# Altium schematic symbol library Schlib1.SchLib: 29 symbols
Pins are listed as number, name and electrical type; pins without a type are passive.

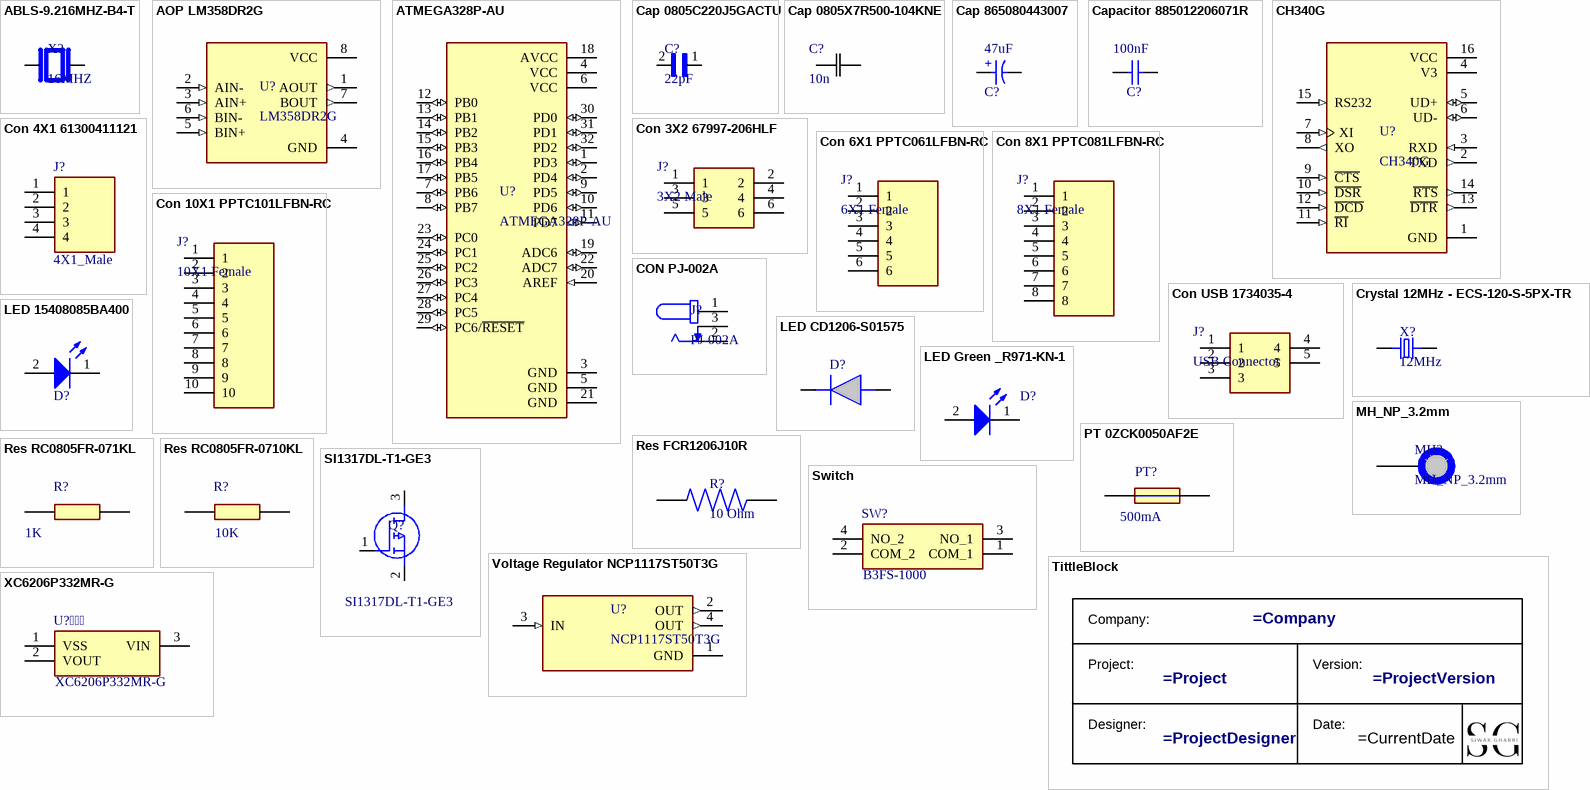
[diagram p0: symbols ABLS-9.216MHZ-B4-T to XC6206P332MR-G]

## ABLS-9.216MHZ-B4-T
designator X?, comment 16MHZ
HC/49US (AT49) SMD LOW PROFILE CRYSTAL; MF: Abracon LLC; MP: ABLS-9.216MHZ-B4-T
footprint XTAL_ABLS-9.216MHZ-B4-T
footprint XTAL_ABLS-9.216MHZ-B4-T
pins: 1, 2

## AOP LM358DR2G
designator U?, comment LM358DR2G
General Purpose Amplifier 2 Circuit - 8-SOIC; MF: ON Semiconductor
footprint SOIC127P600X175-8N
pins: 1 AOUT (out), 2 AIN- (in), 3 AIN+ (in), 4 GND, 5 BIN+ (in), 6 BIN- (in), 7 BOUT (out), 8 VCC (power)

## ATMEGA328P-AU
designator U?
AVR AVRÂ® ATmega Microcontroller IC 8-Bit 20MHz 32KB (16K x 16) FLASH 32-TQFP (7x7); MF: Microchip Technology
footprint QFP80P900X900X120-32N
pins: 1 PD3 (io), 2 PD4 (io), 3 GND (power), 4 VCC (power), 5 GND (power), 6 VCC (power), 7 PB6 (io), 8 PB7 (io), 9 PD5 (io), 10 PD6 (io), 11 PD7 (io), 12 PB0 (io), 13 PB1 (io), 14 PB2 (io), 15 PB3 (io), 16 PB4 (io), 17 PB5 (io), 18 AVCC (power), 19 ADC6 (io), 20 AREF (in), 21 GND (power), 22 ADC7 (io), 23 PC0 (io), 24 PC1 (io), 25 PC2 (io), 26 PC3 (io), 27 PC4 (io), 28 PC5 (io), 29 PC6/~{RESET} (io), 30 PD0 (io), 31 PD1 (io), 32 PD2 (io)

## Cap 0805C220J5GACTU
designator C?, comment 22pF
22pF Â±5% 50V Ceramic Capacitor C0G, NP0 0805 _2012 Metric_; MP: C0805C220J5GACTU; MF: KEMET
footprint CAPC2012X140N
pins: 1, 2

## Cap 0805X7R500-104KNE
designator C?, comment 10n
0.1 µF ±10% 50V Ceramic Capacitor X7R 0805 (2012 Metric); Mfr_Name: Venkel
footprint CAP_C0805_VEN-M
pins: 1, 2

## Cap 865080443007
designator C?, comment 47uF
WCAP-ASLI Aluminum Electrolytic Capacitor, V-Chip, D6.3 x H5.5mm, 47uF, 25V; Manufacturer Part Number: 865080443007; Manufacturer: Wurth Elektronik; Capacitance Tolerance: +/-20%; Dissipation Factor: 14%; Endurance: 2000h; Leakage Current: 11.75uA; Ripple Current: 220mA; Technical Reference: ASED055470M025DVCTBB000
footprint WCAP-ASLI_D6.3H5.5
simulation model 865080443007_47uF
footprint WCAP-ASLI_D6.3H7.7 (Aluminium Electrolytic V-Chip SMT Capacitors, 6.3x7.7mm)
pins: 1 P, 2 N

## Capacitor 885012206071R
designator C?, comment 100nF
WCAP-CSGP Multilayer Ceramic Chip Capacitor, General Purpose, size 0603, X7R, 100nF, 25VDC; Manufacturer Part Number: 885012206071R; Manufacturer: Wurth Elektronik; Case/Size Code: 0603; Capacitance Tolerance: +/-10%; Dissipation Factor: 3.5%; Insulation Resistance: 5GOhm; Rated Voltage (DC): 25V; Technical Reference: X7R0603104K025DFCT20000
footprint WCAP-CSGP_0603_L1.6W0.8H0.8_Reflow
footprint WCAP-CSGP_0603_L1.6W0.8H0.8_Wave
simulation model 0603_885012206071R_100nF
footprint WCAP-CSGP_0603_L1.6W0.8H0.8_Wave (Ceramic Capacitors, 0603, body 1.6x0.8mm)
pins: 1, 2

## CH340G
designator U?
USB Interface Integrated Circuit; MF: WCH
footprint SOIC127P600X180-16N
footprint SOIC127P600X180-16N
pins: 1 GND (power), 2 TXD (out), 3 RXD (in), 4 V3 (power), 5 UD+ (io), 6 UD- (io), 7 XI (in), 8 XO (out), 9 ~{CTS} (in), 10 ~{DSR} (in), 11 ~{RI} (in), 12 ~{DCD} (in), 13 ~{DTR} (out), 14 ~{RTS} (out), 15 RS232 (in), 16 VCC (power)

## Con 3X2 67997-206HLF
designator J?, comment 3X2 Male
Connector; Manufacturer_Name: Amphenol; Manufacturer_Part_Number: 67997-206HLF
footprint HDRV6W67P254_2X3_762X483X858P
pins: 1, 2, 3, 4, 5, 6

## Con 4X1 61300411121
designator J?, comment 4X1_Male
WR-PHD 2.54mm Pin Header THT Straight 4p Wurth Elektronik WR-PHD Series, Series Number 6130, 2.54mm Pitch 4 Way 1 Row Straight PCB Header, Solder Termination; Manufacturer_Part_Number: 61300411121; Geometry.Height: 8.54mm
footprint HDRV4W95P0X254_1X4_1016X254X854P
pins: 1, 2, 3, 4

## Con 6X1 PPTC061LFBN-RC
designator J?, comment 6X1 Female
Connector; Manufacturer_Name: Sullins; Manufacturer_Part_Number: PPTC061LFBN-RC
footprint RHDR6W80P0X254_1X6_1574X254X870P
pins: 1, 2, 3, 4, 5, 6

## Con 8X1 PPTC081LFBN-RC
designator J?, comment 8X1 Female
Connector; Manufacturer_Name: Sullins; Manufacturer_Part_Number: PPTC081LFBN-RC
footprint RHDR8W80P0X254_1X8_2082X254X850P
pins: 1, 2, 3, 4, 5, 6, 7, 8

## Con 10X1 PPTC101LFBN-RC
designator J?, comment 10X1 Female
10 Position Header Connector 0.100" (2.54mm) Through Hole Tin; Manufacturer_Name: Sullins; Manufacturer_Part_Number: PPTC101LFBN-RC
footprint RHDR10W80P0X254_1X10_2590X254X850P
pins: 1, 2, 3, 4, 5, 6, 7, 8, 9, 10

## CON PJ-002A
designator J?, comment PJ-002A
2.0 x 6.5 mm, 2.5 A, Horizontal, Through Hole, Dc Power Jack Connector; MF: CUI Devices
footprint CUI_PJ-002A
footprint CUI_PJ-002A
pins: 1, 2, 3

## Con USB 1734035-4
designator J?, comment USB Connector
Conn Mini USB 2.0 Type B RCP 5 POS 0.8mm Solder RA SMD 5 Terminal 1 Port Automotive T/R; Manufacturer_Name: TE Connectivity; Manufacturer_Part_Number: 1734035-4
footprint 1734035-2USB
footprint 1734035-2USB
pins: 1, 2, 3, 4, 5

## Crystal 12MHz - ECS-120-S-5PX-TR
designator X?, comment 12MHz
12MHz Â±30ppm Crystal Series 50 Ohms HC-49/US; MF: ECS Inc.; MP: ECS-120-S-5PX-TR
footprint XTAL_ECS-120-S-5PX-TR
pins: 1, 2

## LED 15408085BA400
designator D?, comment 15408085BA400  (value not drawn)
WL-SICW SMT Chip LED Infrared Waterclear, size 0805, Infrared, 1.4V, 140°; Manufacturer: Wurth Elektronik; Case/Size Code: 0805; Centroid Wavelength: 845nm; Chip Technology: AlGaAs; Forward Voltage Max: 2V; Peak Wavelength: 850nm; Radiant Intensity: 1.5mW/sr; Radiant Intensity Min: 0.6mW/sr
footprint WL-SICW_0805_L2W1.3H0.8
simulation model 0805_15408085BA400
footprint WL-SICW_0805_L2W1.3H0.8 (SMT Infrared Chip LED Waterclear, body 2x1.3mm)
pins: 1 K, 2 A

## LED CD1206-S01575
designator D?, comment CD1206-S01575  (value not drawn)
Diode Switching 100V 0.15A 4ns SMD1206 Bourns CD1206-S01575 Switching Diode, 150mA, 100V, 4ns, 2-Pin 1206; Geometry.Height: 0.95mm
footprint DIOC3215X95N
pins: 1 K, 2 A

## LED Green _R971-KN-1
designator D?, comment Green LED  (value not drawn)
Standard LEDs - SMD Green, 570nm 26mcd, 20mA; Manufacturer_Name: ams OSRAM; Manufacturer_Part_Number: LG R971-KN-1; Geometry.Height: 0.8mm
footprint LEDC2012X80N
pins: 1 K, 2 A

## MH_NP_3.2mm
designator MH?  (no BOM)
Mounting Hole 3.2mm
footprint MH_NP_3.2mm
pins: 1

## PT 0ZCK0050AF2E
designator PT?, comment 500mA
PTC Resettable Fuse 0.5A(hold) 1A(trip) 9VDC 100A 0.5W 0.1s 0.15Ohm SMD Solder Pad 0805 2.3 X 1.5 X 0.9mm Automotive; Manufacturer_Name: Bel; Manufacturer_Part_Number: 0ZCK0050AF2E
footprint 0ZCK0050AF2E
pins: 1, 2

## Res FCR1206J10R
designator R?, comment 10 Ohm
Res 1206 10 Ohm 5% 1/8W Â±500ppm/Â°C Molded SMD SMD T/R; Resistance: 10; MP: FCR1206J10R; Power_Rating: .125 W; MF: TE Connectivity
footprint RESC3216X70N
pins: 1, 2

## Res RC0805FR-071KL
designator R?, comment 1K
YAGEO - RC0805FR-071KL - SMD Chip Resistor, 1 kohm, +/- 1%, 125 mW, 0805 [2012 Metric], Thick Film, General Purpose; Geometry.Height: 0.6mm
footprint RESC2012X60N
pins: 1, 2

## Res RC0805FR-0710KL
designator R?, comment 10K
YAGEO - RC0805FR-0710KL - SMD Chip Resistor, 10 kohm, +/- 1%, 125 mW, 0805 [2012 Metric], Thick Film, General Purpose; Geometry.Height: 0.6mm
footprint RESC2012X60N
footprint RESC2012X60N
pins: 1, 2

## SI1317DL-T1-GE3
designator Q?
Vishay SI1317DL-T1-GE3 P-channel MOSFET Transistor, 1.1 A, -20 V, 3-Pin SOT-323; Geometry.Height: 1.1mm
footprint SOT65P210X110-3N
pins: 1 G, 2 S, 3 D

## Switch
designator SW?, comment B3FS-1000
Switch Tactile N.O. SPST Flat Plunger Gull Wing 0.05A 24VDC 0.98N SMD Bag; Manufacturer_Name: Omron Electronics; Geometry.Height: 3.3mm
footprint B3FS1000
footprint B3FS1000
pins: 1 COM_1, 2 COM_2, 3 NO_1, 4 NO_2

## TittleBlock
designator ?  (value not drawn)  (graphical)

## Voltage Regulator NCP1117ST50T3G
designator U?, comment NCP1117ST50T3G
Linear Voltage Regulator IC 1 Output 1A SOT-223; MF: ON Semiconductor
footprint SOT230P700X180-4N
pins: 1 GND (power), 2 OUT (out), 3 IN (in), 4 OUT (out)

## XC6206P332MR-G
designator U?
LDO Voltage Regulators 1uA Low Quiescent 3 Terminal, Low ESR Cap. Compatible, Voltage Regulator; Manufacturer_Name: Torex; Geometry.Height: 1.3mm
footprint SOT95P280X130-3N
footprint SOT95P280X130-3N
pins: 1 VSS, 2 VOUT (power), 3 VIN (power)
